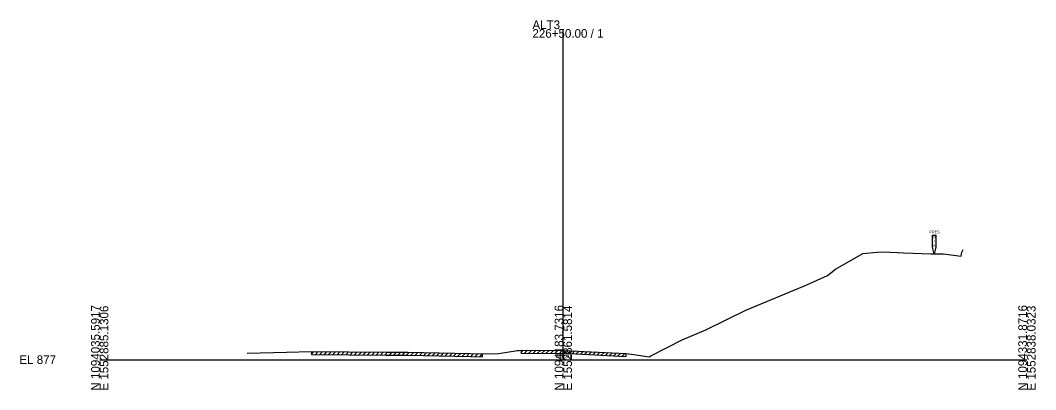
# Model space of a CAD drawing. Extents: x -26 to 1303, y -10 to 19582.
# Drawn here: x -25.7 to 302.8, y -9.7 to 109.7 of the extents above; entities that cross this region are included whole.
import ezdxf

# ---------------------------------------------------------------- set-up
doc = ezdxf.new("R2010")
doc.units = 0
for name, color, linetype in [('Default', 7, 'Continuous'), ('RD_GPK_XS_Cell', 7, 'Continuous'), ('RD_XS_ExGround', 7, 'Continuous'), ('RD_XS_ExPaveRet', 7, 'Continuous'), ('RD_XS_ExRW', 7, 'Continuous'), ('RD_XS_TX_Elev_EX', 7, 'Continuous')]:
    doc.layers.add(name, color=color, linetype=linetype)

msp = doc.modelspace()

# ---------------------------------------------------------------- linework, layer by layer
at = {"layer": 'RD_GPK_XS_Cell'}
for p, q in [((150, 0), (150, 106.9)), ((0, 0), (150, 0)), ((150, 0), (300, 0))]:
    msp.add_line(p, q, dxfattribs=at)
at = {"layer": 'RD_XS_ExGround'}
msp.add_lwpolyline([(47.75, 2.1), (60.45, 2.48), (68.49, 2.64), (92.77, 2.42), (98.41, 2.43), (99.71, 2.43), (119.98, 1.98), (123.76, 1.92), (129.15, 2.04), (135.13, 2.94), (135.69, 2.97), (136.33, 3.04), (149.13, 3), (150.05, 3.01), (170.23, 2.03), (172.8, 1.66), (177.81, 0.96), (178.33, 1.23), (188.43, 6.42), (196.13, 9.69), (209.06, 16.07), (228.82, 24.24), (235.43, 27.24), (238.1, 29.24), (246.86, 34.37), (251.52, 34.74), (253.42, 34.83), (258.12, 34.63), (260.18, 34.59), (268.88, 34.23), (271.46, 34.23), (272.86, 34.18), (273.79, 34.13), (278.7, 33.49), (278.99, 34.72), (279.39, 35.63)], dxfattribs=at)
at = {"layer": 'RD_XS_ExPaveRet'}
for p, q in [((68.49, 2.64), (68.49, 1.64)), ((68.49, 1.8), (69.32, 2.63)), ((69.79, 1.68), (70.73, 2.62)), ((71.19, 1.67), (72.13, 2.61)), ((72.59, 1.65), (73.53, 2.59)), ((73.99, 1.64), (74.93, 2.58)), ((75.39, 1.63), (76.33, 2.57)), ((76.79, 1.62), (77.73, 2.56)), ((78.19, 1.6), (79.14, 2.54)), ((79.6, 1.59), (80.54, 2.53)), ((81, 1.58), (81.94, 2.52)), ((82.4, 1.56), (83.34, 2.51)), ((83.8, 1.55), (84.74, 2.49)), ((85.2, 1.54), (86.14, 2.48)), ((86.6, 1.53), (87.54, 2.47)), ((88, 1.51), (88.95, 2.45)), ((89.41, 1.5), (90.35, 2.44)), ((90.81, 1.49), (91.75, 2.43)), ((92.21, 1.48), (93.15, 2.42)), ((93.62, 1.47), (94.57, 2.42)), ((95.03, 1.47), (95.98, 2.42)), ((96.45, 1.47), (97.4, 2.42)), ((97.86, 1.47), (98.81, 2.42)), ((99.28, 1.47), (100.22, 2.41)), ((100.67, 1.45), (101.6, 2.38)), ((102.06, 1.42), (102.98, 2.35)), ((103.44, 1.39), (104.37, 2.32)), ((104.82, 1.36), (105.75, 2.29)), ((106.21, 1.33), (107.14, 2.26)), ((107.59, 1.3), (108.52, 2.23)), ((108.97, 1.27), (109.9, 2.2)), ((110.36, 1.24), (111.29, 2.17)), ((111.74, 1.21), (112.67, 2.14)), ((113.13, 1.18), (114.06, 2.11)), ((114.51, 1.15), (115.44, 2.08)), ((115.89, 1.12), (116.82, 2.05)), ((117.28, 1.09), (118.21, 2.02)), ((118.66, 1.06), (119.59, 1.99)), ((120.05, 1.03), (120.98, 1.96)), ((121.44, 1), (122.37, 1.94)), ((122.83, 0.98), (123.76, 1.91)), ((123.76, 1.91), (123.76, 0.91)), ((136.33, 3.04), (136.33, 2.04)), ((136.33, 2.38), (136.98, 3.04)), ((137.45, 2.09), (138.39, 3.03)), ((138.86, 2.08), (139.8, 3.03)), ((140.27, 2.08), (141.21, 3.03)), ((141.68, 2.07), (142.62, 3.02)), ((143.09, 2.07), (144.03, 3.02)), ((144.5, 2.07), (145.45, 3.01)), ((145.91, 2.06), (146.86, 3.01)), ((147.32, 2.06), (148.27, 3.01)), ((148.73, 2.05), (149.68, 3.01)), ((150.15, 2.06), (151.05, 2.96)), ((151.5, 1.99), (152.4, 2.9)), ((152.84, 1.93), (153.75, 2.83)), ((154.19, 1.86), (155.1, 2.77)), ((155.54, 1.8), (156.45, 2.7)), ((156.89, 1.73), (157.8, 2.64)), ((158.24, 1.66), (159.14, 2.57)), ((159.59, 1.6), (160.49, 2.5)), ((160.94, 1.53), (161.84, 2.44)), ((162.28, 1.47), (163.19, 2.37)), ((163.63, 1.4), (164.54, 2.31)), ((164.98, 1.34), (165.89, 2.24)), ((166.33, 1.27), (167.24, 2.18)), ((167.68, 1.2), (168.58, 2.11)), ((169.03, 1.14), (169.93, 2.05)), ((170.23, 2.03), (170.23, 1.03))]:
    msp.add_line(p, q, dxfattribs=at)
for points in [[(68.49, 1.69), (92.73, 1.47), (98.4, 1.47), (99.71, 1.47), (119.95, 1.03), (123.76, 0.96)], [(136.33, 2.09), (149.11, 2.05), (150.05, 2.06), (170.23, 1.08)]]:
    msp.add_lwpolyline(points, dxfattribs=at)
at = {"layer": 'RD_XS_ExRW'}
msp.add_lwpolyline([(269.45, 40.25), (270.55, 40.25), (270.55, 36.42), (270, 34.23), (269.45, 36.42)], close=True, dxfattribs=at)

# ---------------------------------------------------------------- texts
at = {"layer": 'Default'}
msp.add_text('-', height=0.0001, dxfattribs=at).set_placement((0, 0))
at = {"layer": 'RD_GPK_XS_Cell'}
for s, p in [('ALT3', (140, 106.9)), ('226+50.00 / 1', (140, 104.1)), ('EL 877', (-26, -1.4))]:
    msp.add_text(s, height=2.8, dxfattribs=at).set_placement(p)
for s, p in [('N 1094035.5917', (0, -10)), ('E 1552885.1306', (2.8, -10)), ('N 1094183.7316', (150, -10)), ('E 1552861.5814', (152.8, -10)), ('N 1094331.8716', (300, -10)), ('E 1552838.0323', (302.8, -10))]:
    msp.add_text(s, height=2.8, rotation=90, dxfattribs=at).set_placement(p)
at = {"layer": 'RD_XS_ExRW'}
for s, p in [('PRES.', (268.45, 40.87)), ('R', (269.71, 39.15)), ('W', (269.53, 36.53)), ('/', (269.83, 37.84))]:
    msp.add_text(s, height=0.875, dxfattribs=at).set_placement(p)
at = {"layer": 'RD_XS_TX_Elev_EX'}
msp.add_text('880.01', height=1.25, dxfattribs=at).set_placement((147.56, 0.59))

doc.saveas('drawing.dxf')
